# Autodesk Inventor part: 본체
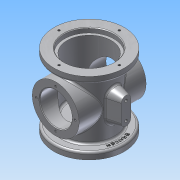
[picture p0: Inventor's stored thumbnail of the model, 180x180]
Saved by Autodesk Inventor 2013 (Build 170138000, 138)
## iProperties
Created: 2018-02
Part Number: 본체
Material: 알루미늄 6061
Document SubType Name: Modeling
Designer: Administrator
Density: 2.71 g/cm^3
Mass: 771.854 g
Surface Area: 821.859 cm^2
Volume: 284.817 cm^3
Author: Administrator
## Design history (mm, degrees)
sketch "스케치1"
  geometry: C1 r 38 at (0, 0); 1 further point
  constraints: 1 centre point, 1 coincident
  dimensions: "d0" = 38 radius of C1
extrude "돌출1" new body sketch "스케치1" stored distance "d1" = 108; taper "d2" = 0 deg
sketch "스케치2"
  geometry: C1 r 38 at (0, 0) reference; C2 r 52.5 at (0, 0)
  constraints: 1 centre point, 1 coincident
  dimensions: "d4" = 105 diameter of C2
extrude "돌출2" join sketch "스케치2" distance "d5" = 10; taper "d6" = 0 deg
sketch "스케치3"
  geometry: C1 r 38 at (0, 0) reference; C2 r 52.5 at (0, 0)
  constraints: 1 centre point, 1 coincident
  dimensions: "d7" = 105 diameter of C2
extrude "돌출3" join sketch "스케치3" distance "d8" = 10; taper "d9" = 0 deg
sketch "스케치4"
  geometry: C1 r 52.5 at (0, 0) reference; C2 r 34 at (0, 0)
  constraints: 1 centre point, 1 coincident
  dimensions: "d10" = 68 diameter of C2
extrude "돌출4" cut sketch "스케치4" distance "d11" = 16; taper "d12" = 0 deg
sketch "스케치5"
  geometry: C1 r 52.5 at (0, 0) reference; C2 r 37 at (0, 0)
  constraints: 1 centre point, 1 coincident
  dimensions: "d13" = 74 diameter of C2
extrude "돌출5" cut sketch "스케치5" distance "d14" = 7; taper "d15" = 0 deg
sketch "스케치6"
  geometry: C1 r 37 at (0, 0) reference; C2 r 33 at (0, 0)
  constraints: 1 centre point, 1 coincident
  dimensions: "d16" = 66 diameter of C2
extrude "돌출6" cut sketch "스케치6" distance "d17" = 79; taper "d18" = 0 deg
node "작업 평면1"
sketch "스케치7"
  geometry: C1 r 35 at (0, 0); 1 further point
  constraints: 1 centre point, 1 coincident
  dimensions: "d20" = 70 diameter of C1
extrude "돌출7" join sketch "스케치7" stored distance "d21" = 79; taper "d22" = 0 deg
sketch "스케치8" dims "d23" = 58
  geometry: C1 r 35 at (0, 0) reference; 5 further points
  constraints: 2 vertical alignment, 1 coincident, 7 other
  dimensions: "d26" = 360 deg dimension on C1.centre point (0, 29) (derived)
hole "구멍1" sketch "스케치8" at (0, 29), (-29, 0), (0, -29), (29, 0) diameter "d28" = 3.242; stored, may be unused: countersink angle "d32" = 90 deg, drill point angle "d34" = 118 deg; dims "d29" = 4, "d30" = 4, "d31" = 2, "d33" = 6
sketch "스케치9"
  geometry: C1 r 35 at (0, 0) reference; C2 r 24 at (0, 0)
  constraints: 1 centre point, 1 coincident
  dimensions: "d35" = 48 diameter of C2
extrude "돌출8" cut sketch "스케치9" stored distance "d36" = 79; taper "d37" = 0 deg
sketch "스케치10" dims "d38" = 90
  geometry: C1 r 37 at (0, 0) reference; C2 r 52.5 at (0, 0) reference; 5 further points
  constraints: 2 vertical alignment, 1 coincident, 7 other
  dimensions: "d41" = 360 deg dimension on C1.centre point (0, 45) (derived)
hole "구멍2" sketch "스케치10" at (0, 45), (-45, 0), (0, -45), (45, 0) diameter "d43" = 3.242; stored, may be unused: countersink angle "d47" = 90 deg, drill point angle "d49" = 118 deg; dims "d44" = 4, "d45" = 4, "d46" = 2, "d48" = 6
sketch "스케치11"
  geometry: C1 r 34 at (0, 0) reference; 1 further point
  constraints: 1 coincident
hole "구멍3" sketch "스케치11" at (0, 0) diameter "d50" = 10; stored, may be unused: countersink angle "d54" = 90 deg, drill point angle "d56" = 118 deg; dims "d51" = 4, "d52" = 4, "d53" = 2, "d55" = 6
node "작업 평면2"
sketch "스케치12"
  geometry: L1 (-13, 7)-(13, 7); L2 (-13, -7)-(13, -7); A1 r 7 centre (13, 0) between (13, 7) and (13, -7); A2 r 7 centre (-13, 0) between (-13, 7) and (-13, -7); 1 further point
  constraints: 4 end point, 4 point on circle, 3 tangent, 2 centre point, 2 horizontal alignment, 1 horizontal
  dimensions: "d58" = 14 diameter of A1; "d59" = 14 diameter of A2; "d60" = 13 distance of A1.centre point (0, 0); "d61" = 13 distance of point (0, 0) A2.centre
extrude "돌출9" join sketch "스케치12" stored distance "d62" = 79; taper "d63" = 15 deg
sketch "스케치13"
  geometry: A1 r 7 centre (0, 13) between (7, 13) and (-7, 13) reference; A2 r 7 centre (0, -13) between (-7, -13) and (7, -13) reference; 3 further points
  constraints: 2 coincident
hole "구멍4" sketch "스케치13" at (0, 13), (0, -13) diameter "d64" = 4.134; stored, may be unused: countersink angle "d68" = 90 deg, drill point angle "d70" = 118 deg; dims "d65" = 6, "d66" = 4, "d67" = 2, "d69" = 8
fillet "모깎기1" dims "d72" = 3
fillet "모깎기2" dims "d73" = 3
fillet "모깎기3" dims "d74" = 3
fillet "모깎기4" dims "d75" = 3
fillet "모깎기5" dims "d76" = 3
fillet "모깎기6" dims "d77" = 3
chamfer "모따기1" distance "d78" = 1; stored, may be unused: second distance "d79" = 2, angle "d80" = 45 deg
sketch "스케치16"
  geometry: C1 r 41 at (0, 0) reference; C2 r 43 at (0, 0)
  constraints: 1 centre point, 1 coincident, 1 other
  dimensions: "d81" = 86 diameter of C2
feature "엠보싱1" sketch "스케치16" dims "d82" = 0.5, "d83" = 0
node "솔리드1"
mirror "대칭1"
other parameters: "d57" = 55
